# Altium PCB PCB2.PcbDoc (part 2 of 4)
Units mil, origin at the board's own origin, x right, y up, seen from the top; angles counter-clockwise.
Board outline 3980.79 x 2126 mil, 6 copper layers (Top Layer, Signal Layer 1, Signal Layer 2, Signal Layer 3, Signal Layer 4, Bottom Layer), stack 61.485 mil thick; 358 components, 190 nets, 1000 pads, 509 vias.
Unrouted connection lines stored in the file: 83.
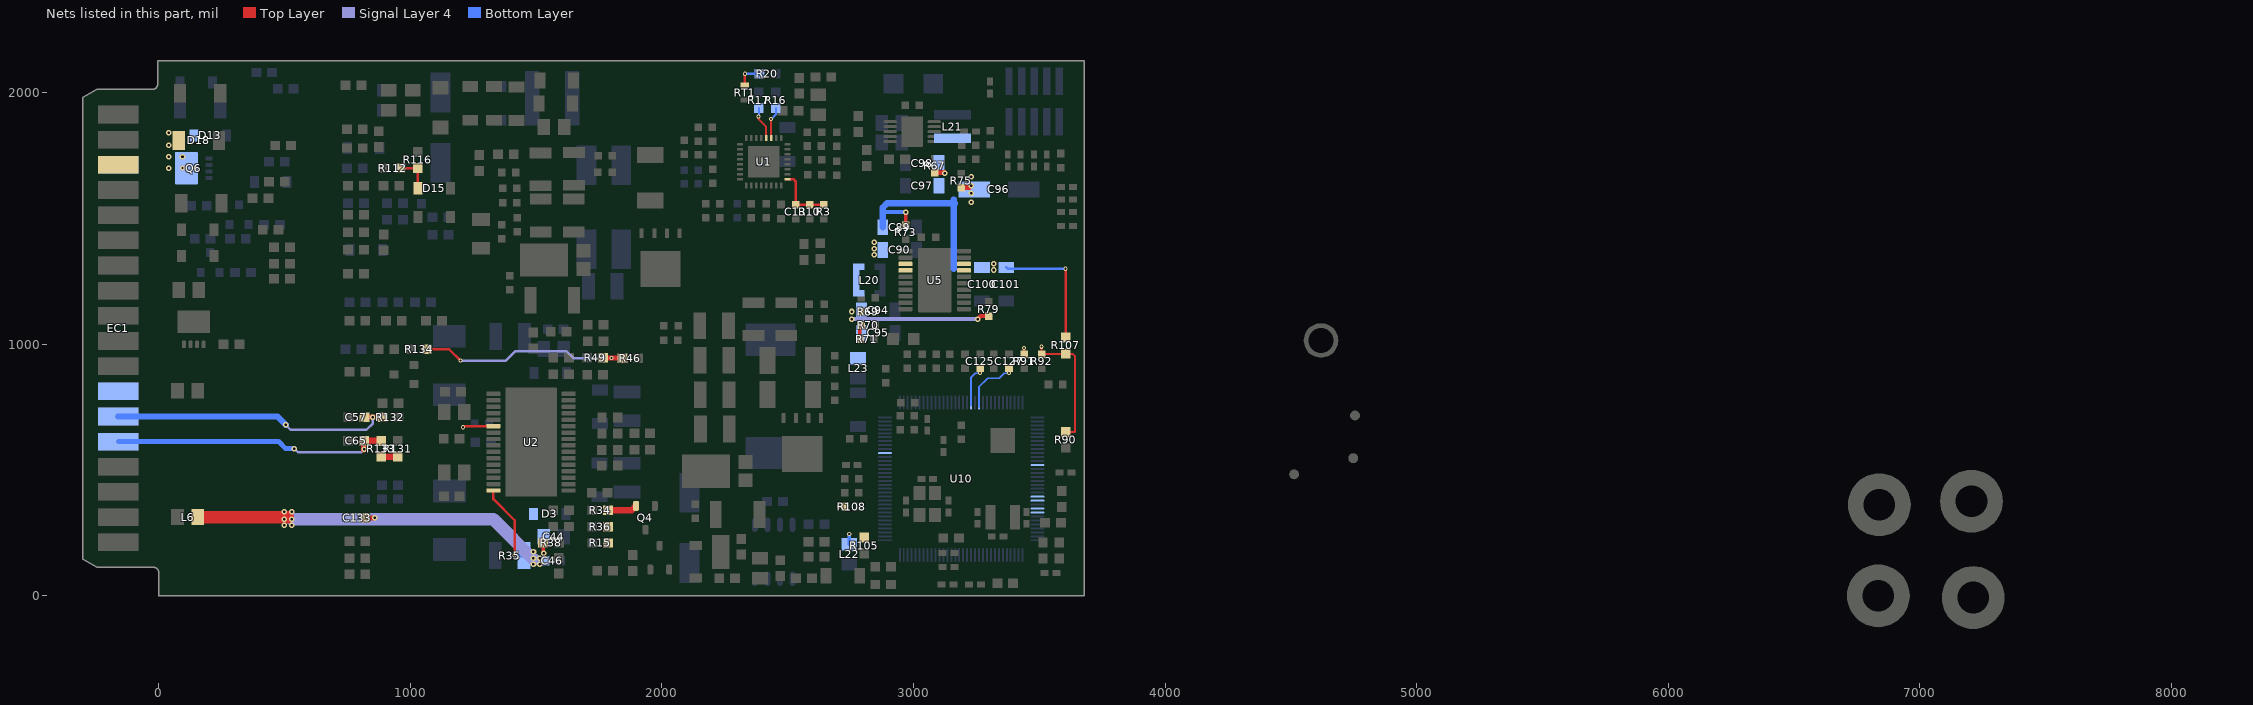
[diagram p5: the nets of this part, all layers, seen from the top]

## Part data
C1 C18: library part CMP-0007272-4, "CAP, CERM, 470 pF, 100 V, +/- 5%, C0G/NP0, 0603", Cap_Case=0603, Manufacturer=MuRata, PartNumber=GRM1885C2A471JA01D, Supplier Part Number 1=490-1367-1-ND, TempCo=C0G/NP0, Tolerance_%=5%, Value1=Unknown, ValueDisplayed=470pF
C2 C10 C19 C28 C29 C35 C36: library part CMP-0007082-4, "CAP, CERM, 0.01 uF, 100 V, +/- 10%, X7R, AEC-Q200 Grade 1, 0603", Cap_Case=0603, Manufacturer=TDK, PartNumber=CGA3E2X7R2A103K080AA, Supplier Part Number 1=445-5812-1-ND, TempCo=X7R, Tolerance_%=10%, Value1="0.235428 ohm", ValueDisplayed=0.01uF
C3 C9 C20 C27 C33: library part CMP-0007469-4, "CAP, CERM, 0.1 uF, 100 V, +/- 10%, X7R, 0603", Cap_Case=0603, Manufacturer=MuRata, PartNumber=GRM188R72A104KA35D, Supplier Part Number 1=490-3285-1-ND, TempCo=X7R, Tolerance_%=10%, Value1=Unknown, ValueDisplayed=0.1uF
C4 C21 C22 C23 C25 C26: library part CMP-0009120-1, "CAP, CERM, 10 uF, 50 V, +/- 20%, X7R, 1210", Cap_Case=1210, Manufacturer=TDK, Supplier Part Number 1=445-14933-1-ND, TempCo=X7R, Tolerance_%=20%, Value1=Unknown, Value2=50V, ValueDisplayed=10uF
C5 C6 C7 C8 C30: library part CMP-0009134-2, "CAP, CERM, 4.7 uF, 100 V, +/- 10%, X7S, 1210", Cap_Case=1210_220, Manufacturer=TDK, PartNumber=C3225X7S2A475K200AB, Supplier Part Number 1=445-6042-1-ND, TempCo=X7S, Tolerance_%=10%, Value1="0.004236 ohm", ValueDisplayed=4.7uF
C11: library part CMP-0011198-2, "CAP, AL, 33 uF, 80 V, +/- 20%, 1.3 ohm, AEC-Q200 Grade 2, SMD", Cap_Case=F, Manufacturer=Panasonic, Supplier Part Number 1=PCE3829CT-ND, Tolerance_%=20%, Value1="1.3 ohm", Value2=80V, ValueDisplayed=33uF
C12 C13 C34 C37: library part CMP-0007432-5, "CAP, CERM, 1000 pF, 50 V, +/- 10%, X7R, 0603", Cap_Case=0603, Manufacturer=MuRata, PartNumber=GRM188R71H102KA01D, Supplier Part Number 1=490-1494-1-ND, TempCo=X7R, Tolerance_%=10%, Value1=Unknown, Value2=50V, ValueDisplayed=1000pF
C14: library part CMP-0007423-4, "CAP, CERM, 0.047 uF, 25 V, +/- 10%, X7R, 0603", Cap_Case=0603, Manufacturer=MuRata, Supplier Part Number 1=490-1522-1-ND, TempCo=X7R, Tolerance_%=10%, Value1=Unknown, Value2=25V, ValueDisplayed=0.047uF
C15 C40: library part CMP-0006822-4, "CAP, CERM, 100 pF, 50 V, +/- 5%, C0G/NP0, 0603", Cap_Case=0603, Manufacturer="Wurth Elektronik", TempCo=C0G/NP0, Tolerance_%=5%, Value1=Unknown, Value2=50V, ValueDisplayed=100pF
C16: library part CMP-0008801-2, "CAP, CERM, 1 uF, 100 V, +/- 10%, X7R, 1206", Cap_Case=1206, Manufacturer=Samsung, PartNumber=CL31B105KCHNNNE, Supplier Part Number 1=1276-1838-1-ND, TempCo=X7R, Tolerance_%=10%, Value1=Unknown, ValueDisplayed=1uF
C17 C24 C31 C32 C42 C45 C49 C57 C65 C66 C74 C85 C87 C88: library part CMP-0007148-4, "CAP, CERM, 3300 pF, 100 V, +/- 10%, X7R, AEC-Q200 Grade 1, 0603", Cap_Case=0603, Manufacturer=MuRata, Supplier Part Number 1=GCM188R72A332KA37D-ND, TempCo=X7R, Tolerance_%=10%, Value1=Unknown, Value2=100V, ValueDisplayed=3300pF
C38 C39: library part CMP-0007499-4, "CAP, CERM, 2.2 uF, 16 V, +/- 10%, X7R, 0603", Cap_Case=0603, Manufacturer=MuRata, PartNumber=GRM188Z71C225KE43, Supplier Part Number 1=81-GRM188Z71C225KE3D, TempCo=X7R, Tolerance_%=10%, Value1=Unknown, Value2=16V, ValueDisplayed=2.2uF
C41: library part CMP-0007099-4, "CAP, CERM, 0.1 uF, 100 V, +/- 10%, X7S, AEC-Q200 Grade 1, 0603", Cap_Case=0603, Manufacturer=TDK, Supplier Part Number 1=445-6938-1-ND, TempCo=X7S, Tolerance_%=10%, Value1="0.04959 ohm", ValueDisplayed=0.1uF
C43 C47: library part CMP-0008791-2, "CAP, CERM, 2.2 uF, 100 V, +/- 20%, X7S, AEC-Q200 Grade 1, 1206_190", Alternate Manufacturer="Taiyo Yuden", Alternate PartNumber=HMJ316BC7225MLHTE, Cap_Case=1206, Manufacturer=TDK, Supplier Part Number 1=445-12947-1-ND, TempCo=X7S, Tolerance_%=20%, Value1=Unknown, Value2=100V, ValueDisplayed=2.2uF
C44 C64: library part CMP-0007981-2, "CAP, CERM, 0.22 uF, 100 V, +/- 10%, X7S, AEC-Q200 Grade 1, 0805", Alternate Manufacturer="Taiyo Yuden", Alternate PartNumber=HMJ212BB7224KGHT, Cap_Case=0805, Manufacturer=TDK, Supplier Part Number 1=445-7959-1-ND, TempCo=X7S, Tolerance_%=10%, Value1="0.019477 ohm", Value2=100V, ValueDisplayed=0.22uF
C46 C63: library part CMP-0007099-4, "CAP, CERM, 0.1 uF, 100 V, +/- 10%, X7S, AEC-Q200 Grade 1, 0603", Cap_Case=0603, Manufacturer=TDK, Supplier Part Number 1=445-6938-1-ND, TempCo=X7S, Tolerance_%=10%, Value1="0.04959 ohm", Value2=100V, ValueDisplayed=0.1uF
C48 C62: library part CMP-0007387-4, "CAP, CERM, 2200 pF, 16 V, +/- 10%, X7R, 0603", Cap_Case=0603, Manufacturer=MuRata, Supplier Part Number 1=GRM188R71C222KA01D-ND, TempCo=X7R, Tolerance_%=10%, Value1=Unknown, Value2=16V, ValueDisplayed=2200pF
C50 C60: library part CMP-0007077-5, "CAP, CERM, 0.1 uF, 25 V, +/- 10%, X7R, AEC-Q200 Grade 1, 0603", Cap_Case=0603, Manufacturer=TDK, Supplier Part Number 1=445-5667-1-ND, TempCo=X7R, Tolerance_%=10%, Value1=Unknown, Value2=25V, ValueDisplayed=0.1uF
C51 C61: library part CMP-0007467-4, "CAP, CERM, 1000 pF, 100 V, +/- 10%, X7R, 0603", Cap_Case=0603, Manufacturer=MuRata, Supplier Part Number 1=490-1472-1-ND, TempCo=X7R, Tolerance_%=10%, Value1=Unknown, Value2=100V, ValueDisplayed=1000pF
C52 C59: library part CMP-0009148-2, "CAP, CERM, 1.5 uF, 100 V, +/- 10%, X7R, AEC-Q200 Grade 1, 1210", Cap_Case=1210_220, Manufacturer=TDK, Supplier Part Number 1=445-13014-1-ND, TempCo=X7R, Tolerance_%=10%, Value1="0.003867 ohm", Value2=100V, ValueDisplayed=1.5uF
C53 C55: library part CMP-0007136-5, "CAP, CERM, 1 uF, 16 V, +/- 10%, X7R, AEC-Q200 Grade 1, 0603", Cap_Case=0603, Manufacturer=MuRata, Supplier Part Number 1=490-5241-6-ND, TempCo=X7R, Tolerance_%=10%, Value1=Unknown, Value2=16V, ValueDisplayed=1uF
C54 C56 C58: library part CMP-0085536-1, "CAP, CERM, 0.1 µF, 16 V,+/- 10%, X7R, 0603", Cap_Case=0603, Manufacturer="Samsung Electro-Mechanics", TempCo=X7R, Tolerance_%=10%, Value2=16V, ValueDisplayed=0.1µF
C67 C71 C72 C75 C80: library part CMP-0007725-2, "CAP, CERM, 0.1 uF, 50 V, +/- 10%, X7R, AEC-Q200 Grade 0, 0805", Cap_Case=0805, Manufacturer=Kemet, Supplier Part Number 1=399-6928-1-ND, TempCo=X7R, Tolerance_%=10%, Value1=Unknown, Value2=50V, ValueDisplayed=0.1uF
C68: library part CMP-0007143-4, "CAP, CERM, 0.01 uF, 50 V, +/- 10%, X7R, AEC-Q200 Grade 1, 0603", Cap_Case=0603, Manufacturer=MuRata, Supplier Part Number 1=490-4778-1-ND, TempCo=X7R, Tolerance_%=10%, Value1=Unknown, Value2=50V, ValueDisplayed=0.01uF
C69 C70 C76 C77 C78 C79: library part CMP-0008702-2, "CAP, CERM, 4.7 uF, 50 V, +/- 10%, X7R, 1206", Cap_Case=1206_180, Manufacturer=TDK, Supplier Part Number 1=445-8032-1-ND, TempCo=X7R, Tolerance_%=10%, Value1="0.003158 ohm", Value2=50V, ValueDisplayed=4.7uF
C73: library part CMP-0011177-2, "CAP, AL, 100 uF, 50 V, +/- 20%, 0.34 ohm, AEC-Q200 Grade 2, SMD", Cap_Case=F, Manufacturer=Panasonic, Supplier Part Number 1=PCE3809CT-ND, Tolerance_%=20%, Value1="0.34 ohm", Value2=50V, ValueDisplayed=100uF
C81: library part CMP-0860912-1, "CAP, CERM, 220 pF, 100 V,+/- 5%, C0G/NP0, AEC-Q200 Grade 1, 0603", Cap_Case=0603, Manufacturer=MuRata, TempCo=C0G/NP0, Tolerance_%=5%, Value2=100V, ValueDisplayed=220pF
C82 C83: library part CMP-0080704-2, "CAP, CERM, 15 pF, 100 V,+/- 5%, C0G/NP0, AEC-Q200 Grade 1, 0603", Cap_Case=0603, Manufacturer=MuRata, Supplier Part Number 1=490-4941-1-ND, TempCo=C0G/NP0, Tolerance_%=5%, Value2=100V, ValueDisplayed=15pF
C86 C133 C134: library part CMP-0007468-5, "CAP, CERM, 0.01 uF, 100 V, +/- 10%, X7R, 0603", Cap_Case=0603, Manufacturer=MuRata, Supplier Part Number 1=GRM188R72A103KA01D-ND, TempCo=X7R, Tolerance_%=10%, Value1=Unknown, Value2=100V, ValueDisplayed=0.01uF
C89 C90 C94 C95 C97 C98 C100 C101 C110: library part CMP-0008965-2, "CAP, CERM, 10 uF, 25 V, +/- 10%, X7R, 1206", Cap_Case=2220, Manufacturer=MuRata, PartNumber=GRM31CR71E106KA12L, Supplier Part Number 1=81-GRM31CR71E106KA12, TempCo=X7R, Tolerance_%=10%, Value1=Unknown, Value2=25V, ValueDisplayed=10uF
C91: library part CMP-0007378-5, "CAP, CERM, 0.1 uF, 16 V, +/- 10%, X7R, 0603", Cap_Case=0603, Manufacturer=MuRata, PartNumber=GRM188R71C104KA01D, Supplier Part Number 1=490-1532-1-ND, TempCo=X7R, Tolerance_%=10%, Value1=Unknown, Value2=16V, ValueDisplayed=0.1uF
C92: library part CMP-0007980-2, "CAP, CERM, 1 uF, 100 V, +/- 10%, X7S, AEC-Q200 Grade 1, 0805", Cap_Case=0805, Manufacturer=TDK, Supplier Part Number 1=445-6974-1-ND, TempCo=X7S, Tolerance_%=10%, Value1="0.008255 ohm", Value2=100V, ValueDisplayed=1uF
C93: library part CMP-0007969-2, "CAP, CERM, 0.1 uF, 100 V, +/- 10%, X7R, AEC-Q200 Grade 1, 0805", Cap_Case=0805, Manufacturer=TDK, Supplier Part Number 1=445-5827-1-ND, TempCo=X7R, Tolerance_%=10%, Value1="0.020726 ohm", Value2=100V, ValueDisplayed=0.1uF
C96: library part CMP-0010733-1, "CAP, AL, 100 uF, 16 V, +/- 20%, 0.26 ohm, AEC-Q200 Grade 2, SMD", Cap_Case=D, Manufacturer=Panasonic, Supplier Part Number 1=PCE4533CT-ND, Tolerance_%=20%, Value1="0.26 ohm", Value2=16V, ValueDisplayed=100uF
C99: library part CMP-0007405-4, "CAP, CERM, 1 uF, 25 V, +/- 10%, X7R, 0603", Cap_Case=0603, Manufacturer=MuRata, PartNumber=GRM188R71E105KA12D, Supplier Part Number 1=490-5307-1-ND, TempCo=X7R, Tolerance_%=10%, Value1=Unknown, Value2=25V, ValueDisplayed=1uF
C102: library part CMP-0006503-2, "CAP, CERM, 5 pF, 100 V, +/- 5%, C0G/NP0, 0402", Cap_Case=0402, Manufacturer=MuRata, Supplier Part Number 1=490-7291-1-ND, TempCo=C0G/NP0, Tolerance_%=5%, Value1=Unknown, Value2=100V, ValueDisplayed=5pF
C103: library part CMP-0007086-4, "CAP, CERM, 0.022 uF, 100 V, +/- 10%, X7R, AEC-Q200 Grade 1, 0603", Cap_Case=0603, Manufacturer=TDK, Supplier Part Number 1=445-5814-1-ND, TempCo=X7R, Tolerance_%=10%, Value1="0.083542 ohm", Value2=100V, ValueDisplayed=0.022uF
C104: library part CMP-0007453-4, "CAP, CERM, 3900 pF, 50 V, +/- 10%, X7R, 0603", Cap_Case=0603, Manufacturer=MuRata, PartNumber=GRM188R71H392KA01D, Supplier Part Number 1=490-1504-1-ND, TempCo=X7R, Tolerance_%=10%, Value1=Unknown, Value2=50V, ValueDisplayed=3900pF
C105 C106 C107 C108 C109 C113 C115 C119: library part CMP-0006641-2, "CAP, CERM, 0.1 uF, 16 V, +/- 10%, X7R, 0402", Cap_Case=0402, Manufacturer=MuRata, Supplier Part Number 1=490-3261-1-ND, TempCo=X7R, Tolerance_%=10%, Value1=Unknown, Value2=16V, ValueDisplayed=0.1uF
C111: library part CMP-0007339-5, "CAP, CERM, 2.2 uF, 16 V, +/- 10%, X5R, 0603", Cap_Case=0603, Manufacturer=MuRata, Supplier Part Number 1=490-3296-1-ND, TempCo=X5R, Tolerance_%=10%, Value1=Unknown, Value2=16V, ValueDisplayed=2.2uF
C112: library part CMP-0006563-2, "CAP, CERM, 1 uF, 10 V, +/- 10%, X5R, 0402", Cap_Case=0402, Manufacturer=MuRata, Supplier Part Number 1=490-3890-1-ND, TempCo=X5R, Tolerance_%=10%, Value1=Unknown, Value2=10V, ValueDisplayed=1uF
C114: library part CMP-0008968-2, "CAP, CERM, 2.2 uF, 50 V, +/- 10%, X7R, 1206", Cap_Case=1206, Manufacturer=MuRata, PartNumber=GRM31CR71H225KA88L, Supplier Part Number 1=490-3367-1-ND, TempCo=X7R, Tolerance_%=10%, Value1=Unknown, Value2=50V, ValueDisplayed=2.2uF
C116 C117 C118 C124 C125 C126 C127 C128 C129 C130 C131 C132: library part CMP-0006921-4, "CAP, CERM, 330 pF, 50 V, +/- 10%, X7R, 0603", Cap_Case=0603, Manufacturer=Kemet, Supplier Part Number 1=399-1073-1-ND, TempCo=X7R, Tolerance_%=10%, Value1=Unknown, Value2=50V, ValueDisplayed=330pF
C120 C121 C122 C123: library part CMP-0006415-2, "CAP, CERM, 12 pF, 50 V, +/- 5%, C0G/NP0, 0402", Cap_Case=0402, Manufacturer=MuRata, Supplier Part Number 1=14T3292, TempCo=C0G/NP0, Tolerance_%=5%, Value1=Unknown, Value2=50V, ValueDisplayed=12pF
D1 D2: library part CMP-0028754-2, "Diode, Schottky, 100 V, 3 A, AEC-Q101, PowerDI5", Manufacturer="Diodes Inc.", Value1=3A, Value2=0.76V
D3 D4: library part CMP-0080761-2, "Diode, Switching, 100 V, 0.25 A, AEC-Q101, SOD-123", Manufacturer=Vishay-Semiconductor, Value1=0.25A, Value2=1.25V
D5: library part CMP-0085086-1, "Diode, TVS, Bi, 28 V, 45.4 Vc, 400 W, 8.8 A, AEC-Q101, SMA (non-polarized)", Manufacturer=Littelfuse, Value1=45.4V
D6 D7 D13 D14: library part CMP-0750148-1, "Diode, Switching, 100 V, 0.3 A, AEC-Q101, SOD-123", Manufacturer="Diodes Inc.", Value1=0.3A, Value2=1.25V
D8 D9 D15 D16: library part CMP-0077593-3, "Diode, Zener, 3 V, 500 mW, SOD-123", Manufacturer=Vishay-Semiconductor, Power_W=500mW, Value1=0.5W
D10: library part CMP-0002980-3, "LED, Green, SMD", Color=Green, Manufacturer=OSRAM, PartNumber="LG R971-KN-1", Value1=W, Value2=2.2V
D11: library part CMP-0028837-2, "Diode, Schottky, 60 V, 2 A, AEC-Q101, SMA", Manufacturer=Vishay-Semiconductor, PartNumber=SS26SHE3_A/H, Value1=2A, Value2=0.75V
D12 D18 D19 D20: library part CMP-0028823-2, "Diode, Schottky, 30 V, 5 A, AEC-Q101, SMAF", Manufacturer="Fairchild Semiconductor", Value1=5A, Value2=0.54V
D17: library part CMP-0077570-3, "Diode, Zener, 10 V, 500 mW, AEC-Q101, SOD-123", Manufacturer=Vishay-Semiconductor, Power_W=500mW, Value1=0.5W
D21: library part CMP-0029032-2, "Diode, Switching, 100 V, 0.2 A, SOD-123", Manufacturer="ON Semiconductor", Value1=0.2A, Value2=1V
EC1: library part CMP-0077097-2, "Card Edge Footprint, 2.54mm, 18x2", Manufacturer="Sullins Connector Solutions"
FID1 FID2 FID3: library part CMP-0077181-1, "Fiducial mark.  There is nothing to buy or mount.", Manufacturer=N/A
H1 H2 H3 H4: library part CMP-0003617-1, "Machine Screw, Round, #4-40 x 1/4, Nylon, Philips panhead", Manufacturer="B&F Fastener Supply", Supplier Part Number 1=H542-ND
H5 H6 H7 H8: library part CMP-0003610-1, "Standoff, Hex, 0.5\"L #4-40 Nylon", Manufacturer=Keystone, Supplier Part Number 1=36-1902C-ND
H9 H10 H11 H12: library part CMP-0003620-1, "Bumpon, Hemisphere, 0.44 X 0.20, Clear", Manufacturer=3M, Supplier Part Number 1=SJ5303-7-ND
J3: library part CMP-0075629-2, "Header, 1.27mm, 5x2, Gold, Black, SMT", Color=Black, Current_A=3.3A, Manufacturer=Samtec, PartNumber=FTSH-105-01-F-DV, Supplier Part Number 1=SAM8795-ND
L1: library part CMP-0084138-1, "Inductor, Shielded, 22 µH, 6.9 A, 0.0341 ohm, AEC-Q200 Grade 0, SMD", Manufacturer=TDK, Value1="0.0341 ohm", Value2=6.9A, ValueDisplayed=22µH
L2 L5 L6 L8 L9: library part CMP-0003069-1, "Ferrite Bead, 33 ohm @ 100 MHz, 4 A, 0805", Manufacturer="Wurth Elektronik", Supplier Part Number 1=732-4636-1-ND, Value1="0.008 ohm", Value2=4A, ValueDisplayed="33 ohm"
L3: library part CMP-0012870-2, "Coupled inductor, 33 uH, 5.6 A, 0.15 ohm, TH", Manufacturer=Coilcraft, ValueDisplayed=33uH
L4 L7: library part CMP-0081480-2, "Inductor, Shielded, Metal Composite, 68 µH, 1.8 A, 0.316 ohm, SMD", Manufacturer=TDK, Value1="0.316 ohm", Value2=1.8A, ValueDisplayed=68µH
L10: library part CMP-0061017-2, "Inductor, Shielded, Composite, 3.3 µH, 8 A, 0.02081 ohm, AEC-Q200 Grade 1, SMD", Manufacturer=Coilcraft, Value1="0.02081 ohm", Value2=8A, ValueDisplayed=3.3µH
L20: library part CMP-0060436-1, "Inductor, Shielded Drum Core, Ferrite, 2.2 uH, 1.1 A, 0.22 ohm, SMD", Manufacturer=Coilcraft, Value1="0.22 ohm", Value2=1.1A, ValueDisplayed=2.2uH
L21: library part CMP-0061649-2, "Inductor, Shielded, Composite, 15 uH, 2.8 A, 0.109 ohm, SMD", Manufacturer=Coilcraft, PartNumber=XAL4040-153MEB, Supplier Part Number 1=994-XAL4040-153MEB, Value1="0.109 ohm", Value2=2.8A, ValueDisplayed=15uH
L22: library part CMP-0003363-1, "Ferrite Bead, 220 ohm @ 100 MHz, 2 A, 0805", Manufacturer=MuRata, PartNumber=BLM21PG221SN1D, Supplier Part Number 1=490-1054-1-ND, Value1="0.045 ohm", Value2=2A, ValueDisplayed="220 ohm"
L23: library part CMP-0003306-1, "Ferrite Bead, 60 ohm @ 100 MHz, 3 A, 0805", Manufacturer="Taiyo Yuden", PartNumber=BKP2125HS600-T, Supplier Part Number 1=587-1932-1-ND, Value1="0.025 ohm", Value2=3A, ValueDisplayed="60 ohm"
LBL1: library part CMP-0003625-1, "Thermal Transfer Printable Labels, 0.650\" W x 0.200\" H - 10,000 per roll", Manufacturer=Brady, Supplier Part Number 1=97C5133
Logo1: library part CMP-0074838-1, "Texas Instrument Corporate Signature"
Logo2: library part CMP-0074844-1
Logo3: library part CMP-0074847-1, "FCC_disclaimer"
Logo4: library part CMP-0074769-1
Q1 Q3: library part CMP-0086155-1, "MOSFET, N-CH, 80 V, 60 A, AEC-Q101, PowerPAK_SO-8L", Alternate Manufacturer=None, Manufacturer=Vishay-Siliconix, Value1="? ohm", Value2="36 nC"
Q4: library part CMP-0000092-3, "MOSFET, P-CH, -20 V, -3.7 A, SOT-23", Alternate Manufacturer=None, Manufacturer=Vishay-Siliconix, Value1=0.03, Value2="12.5 nC"
Q5: library part CMP-0000419-2, "Transistor, NPN, 40 V, 0.2 A, SOT-23", Manufacturer="ON Semiconductor", Supplier Part Number 1=MMBT3904LT1GOSCT-ND, Value1="0.2 A", Value2=300
Q6: library part CMP-0000123-4, "MOSFET, P-CH, -30 V, -13.9 A, PowerPAK 1212", Alternate Manufacturer=None, Manufacturer=Vishay-Siliconix, Value1=0.022, Value2="20.5 nC"
Q7 Q8 Q10: library part CMP-0087176-1, "MOSFET N-CH 100V 170MA SOT23-3", Manufacturer="Diodes Incorporated"
Q9: library part CMP-0000752-2, "MOSFET, N-CH, 40 V, 12 A, AEC-Q101, PowerPAK 1212", Alternate Manufacturer=None, Manufacturer=Vishay-Siliconix, Supplier Part Number 1=SQS840EN-T1_GE3-ND, Value1=0, Value2="15 nC"
R1 R18: library part CMP-0016180-3, "RES, 7.5, 5%, 0.75 W, AEC-Q200 Grade 0, 2010", Manufacturer=Vishay-Dale, PartNumber=CRCW20107R50JNEF, Power_W=750mW, Supplier Part Number 1=541-7.5WCT-ND, TempCo="200 ppm/C", Tolerance_%=5%, Value2=0.75W, Value_Code=7R50, ValueDisplayed=7.5
R2 R14 R25: library part CMP-0025697-4, "RES, 0, 5%, 0.1 W, AEC-Q200 Grade 0, 0603", Manufacturer=Vishay-Dale, Power_W=100mW, Supplier Part Number 1=541-0.0GCT-ND, TempCo="200 ppm/C", Tolerance_%=5%, Value2=0.1W, Value_Code=0000, ValueDisplayed=0
R3 R58 R60 R116 R118 R121: library part CMP-0021990-4, "RES, 100 k, 1%, 0.1 W, AEC-Q200 Grade 0, 0603", Manufacturer=Vishay-Dale, Power_W=100mW, Supplier Part Number 1=541-100KHCT-ND, TempCo="100 ppm/C", Tolerance_%=1%, Value2=0.1W, Value_Code=100k
R4 R30: library part CMP-0021991-4, "RES, 100, 1%, 0.1 W, AEC-Q200 Grade 0, 0603", Manufacturer=Vishay-Dale, PartNumber=CRCW0603100RFKEA, Power_W=100mW, Supplier Part Number 1=541-100HCT-ND, TempCo="100 ppm/C", Tolerance_%=1%, Value2=0.1W, Value_Code=100R, ValueDisplayed=100
R5 R8 R21 R38 R40: library part CMP-0022200-4, "RES, 200 k, 1%, 0.1 W, AEC-Q200 Grade 0, 0603", Manufacturer=Vishay-Dale, Power_W=100mW, Supplier Part Number 1=541-200KHCT-ND, TempCo="100 ppm/C", Tolerance_%=1%, Value2=0.1W, Value_Code=200k
R6 R9 R32: library part CMP-0016519-2, "RES, 0.04, 1%, 1 W, 2010", Manufacturer="Stackpole Electronics Inc", Power_W=1W, Supplier Part Number 1=CSRN2010FK40L0CT-ND, TempCo="250 ppm/C", Tolerance_%=1%, Value_Code=R040, ValueDisplayed=0.04
R7 R13 R16 R17 R20 R46 R48 R50 R99 R102 R103 R105: library part CMP-0023341-3, "RES, 10.0 k, 1%, 0.1 W, AEC-Q200 Grade 0, 0603", Manufacturer="Stackpole Electronics Inc", Power_W=100mW, Supplier Part Number 1=RMCF0603FT10K0CT-ND, TempCo="100 ppm/C", Tolerance_%=1%, Value2=0.1W, Value_Code=10k0, ValueDisplayed=10.0k
R10: library part CMP-0022450-4, "RES, 4.12 k, 1%, 0.1 W, AEC-Q200 Grade 0, 0603", Manufacturer=Vishay-Dale, Power_W=100mW, Supplier Part Number 1=541-4.12KHCT-ND, TempCo="100 ppm/C", Tolerance_%=1%, Value2=0.1W, Value_Code=4k12, ValueDisplayed=4.12k
R11: library part CMP-0021009-3, "RES, 1.00, 1%, 0.125 W, AEC-Q200 Grade 0, 0805", Manufacturer=Vishay-Dale, PartNumber=CRCW08051R00FKEA, Power_W=125mW, Supplier Part Number 1=72M6849, TempCo="100 ppm/C", Tolerance_%=1%, Value2=0.125W, Value_Code=1R00, ValueDisplayed=1.00
R12: library part CMP-0022687-3, "RES, 14.7 k, 1%, 0.1 W, AEC-Q200 Grade 0, 0603", Manufacturer=Panasonic, Power_W=100mW, Supplier Part Number 1=P14.7KHCT-ND, TempCo="100 ppm/C", Tolerance_%=1%, Value2=0.1W, Value_Code=14k7, ValueDisplayed=14.7k
R15 R28 R90 R107: library part CMP-0022002-4, "RES, 10.0 M, 1%, 0.1 W, AEC-Q200 Grade 0, 0603", Manufacturer=Vishay-Dale, Power_W=100mW, Supplier Part Number 1=541-10.0MHCT-ND, TempCo="100 ppm/C", Tolerance_%=1%, Value2=0.1W, Value_Code=10M0, ValueDisplayed=10.0M
R19: library part CMP-0017835-2, "RES, 0.165, 1%, 0.25 W, 1206", Manufacturer="Yageo America", Power_W=250mW, Supplier Part Number 1=311-0.165ANCT-ND, TempCo="75 ppm/C", Tolerance_%=1%, Value2=0.25W, Value_Code=R165, ValueDisplayed=0.165
R22: library part CMP-0022408-4, "RES, 402 k, 1%, 0.1 W, AEC-Q200 Grade 0, 0603", Manufacturer=Vishay-Dale, Power_W=100mW, Supplier Part Number 1=541-402KHCT-ND, TempCo="100 ppm/C", Tolerance_%=1%, Value2=0.1W, Value_Code=402k
R23 R39 R41 R44 R54 R55 R56 R57 R59 R61 R62 R66 R111 R112 R113 R114 R115 R117 R120 R123 R124 R125 R126 R128 R129 R130 R131 R135 R136 R140 R141: library part CMP-0021998-4, "RES, 10.0 k, 1%, 0.1 W, AEC-Q200 Grade 0, 0603", Manufacturer=Vishay-Dale, Power_W=100mW, Supplier Part Number 1=541-10.0KHCT-ND, TempCo="100 ppm/C", Tolerance_%=1%, Value2=0.1W, Value_Code=10k0, ValueDisplayed=10.0k
R24 R47: library part CMP-0021990-4, "RES, 100 k, 1%, 0.1 W, AEC-Q200 Grade 0, 0603", Manufacturer=Vishay-Dale, PartNumber=CRCW0603100KFKEA, Power_W=100mW, Supplier Part Number 1=541-100KHCT-ND, TempCo="100 ppm/C", Tolerance_%=1%, Value2=0.1W, Value_Code=100k
R26 R27: library part CMP-0022003-4, "RES, 10.0, 1%, 0.1 W, AEC-Q200 Grade 0, 0603", Manufacturer=Vishay-Dale, PartNumber=CRCW060310R0FKEA, Power_W=100mW, Supplier Part Number 1=541-10.0HCT-ND, TempCo="100 ppm/C", Tolerance_%=1%, Value2=0.1W, Value_Code=10R0, ValueDisplayed=10.0
R29: library part CMP-0022665-4, "RES, 9.09 k, 1%, 0.1 W, AEC-Q200 Grade 0, 0603", Manufacturer=Vishay-Dale, Power_W=100mW, Supplier Part Number 1=541-9.09KHCT-ND, TempCo="100 ppm/C", Tolerance_%=1%, Value2=0.1W, Value_Code=9k09, ValueDisplayed=9.09k
R31: library part CMP-0022036-4, "RES, 130 k, 1%, 0.1 W, AEC-Q200 Grade 0, 0603", Manufacturer=Vishay-Dale, Power_W=100mW, Supplier Part Number 1=541-130KHCT-ND, TempCo="100 ppm/C", Tolerance_%=1%, Value2=0.1W, Value_Code=130k
R33: library part CMP-0022440-4, "RES, 47.5, 1%, 0.1 W, AEC-Q200 Grade 0, 0603", Manufacturer=Vishay-Dale, Power_W=100mW, Supplier Part Number 1=541-47.5HCT-ND, TempCo="100 ppm/C", Tolerance_%=1%, Value2=0.1W, Value_Code=47R5, ValueDisplayed=47.5
R34 R49: library part CMP-0022068-4, "RES, 15.8 k, 1%, 0.1 W, AEC-Q200 Grade 0, 0603", Manufacturer=Vishay-Dale, Power_W=100mW, Supplier Part Number 1=541-15.8KHCT-ND, TempCo="100 ppm/C", Tolerance_%=1%, Value2=0.1W, Value_Code=15k8, ValueDisplayed=15.8k
R35 R52: library part CMP-0015068-3, "RES, 0.1, 1%, 0.33 W, AEC-Q200 Grade 1, 1210", Alternate Manufacturer=Yageo, Alternate PartNumber=RL1210FR-070R1L, Manufacturer=Panasonic, Power_W=330mW, Supplier Part Number 1=P100NACT-ND, TempCo="100 ppm/C", Tolerance_%=1%, Value2=0.33W, Value_Code=R100, ValueDisplayed=0.1
R36 R43 R51 R108 R109 R110 R122 R127 R132 R133 R134 R137 R138 R139 R142 R143: library part CMP-0022109-5, "RES, 1.00 k, 1%, 0.1 W, AEC-Q200 Grade 0, 0603", Manufacturer=Vishay-Dale, Power_W=100mW, Supplier Part Number 1=541-1.00KHCT-ND, TempCo="100 ppm/C", Tolerance_%=1%, Value2=0.1W, Value_Code=1k00, ValueDisplayed=1.00k
R37 R53: library part CMP-0022324-4, "RES, 30.1 k, 1%, 0.1 W, AEC-Q200 Grade 0, 0603", Manufacturer=Vishay-Dale, Power_W=100mW, Supplier Part Number 1=541-30.1KHCT-ND, TempCo="100 ppm/C", Tolerance_%=1%, Value2=0.1W, Value_Code=30k1, ValueDisplayed=30.1k
R42 R45: library part CMP-0025874-4, "RES, 0, 5%, 0.1 W, AEC-Q200 Grade 0, 0603", Manufacturer=Panasonic, Power_W=100mW, Supplier Part Number 1=P0.0GCT-ND, TempCo="600 ppm/C", Tolerance_%=5%, Value2=0.1W, Value_Code=0000, ValueDisplayed=0
R63 R64 R65 R100 R144: library part CMP-0022003-4, "RES, 10.0, 1%, 0.1 W, AEC-Q200 Grade 0, 0603", Manufacturer=Vishay-Dale, Power_W=100mW, Supplier Part Number 1=541-10.0HCT-ND, TempCo="100 ppm/C", Tolerance_%=1%, Value2=0.1W, Value_Code=10R0, ValueDisplayed=10.0
R67 R70 R79: library part CMP-0023133-5, "RES, 47.0 k, 1%, 0.1 W, 0603", Manufacturer=Yageo, PartNumber=RC0603FR-0747KL, Power_W=100mW, Supplier Part Number 1=311-47.0KHRCT-ND, TempCo="100 ppm/C", Tolerance_%=1%, Value2=0.1W, Value_Code=47k0, ValueDisplayed=47.0k
R68: library part CMP-0022701-2, "RES, 402 k, 1%, 0.1 W, AEC-Q200 Grade 0, 0603", Manufacturer=Panasonic, Power_W=100mW, Supplier Part Number 1=P402KHCT-ND, TempCo="100 ppm/C", Tolerance_%=1%, Value2=0.1W, Value_Code=402k
R69: library part CMP-0023026-5, "RES, 31.6 k, 1%, 0.1 W, 0603", Manufacturer=Yageo, PartNumber=RC0603FR-0731K6L, Power_W=100mW, Supplier Part Number 1=311-31.6KHRCT-ND, TempCo="100 ppm/C", Tolerance_%=1%, Value2=0.1W, Value_Code=31k6, ValueDisplayed=31.6k
R71: library part CMP-0023235-5, "RES, 680, 1%, 0.1 W, 0603", Manufacturer=Yageo, PartNumber=RC0603FR-07680RL, Power_W=100mW, Supplier Part Number 1=311-680HRCT-ND, TempCo="100 ppm/C", Tolerance_%=1%, Value2=0.1W, Value_Code=680R, ValueDisplayed=680
R72 R77: library part CMP-0021998-4, "RES, 10.0 k, 1%, 0.1 W, AEC-Q200 Grade 0, 0603", Manufacturer=Vishay-Dale, PartNumber=CRCW060310K0FKEA, Power_W=100mW, Supplier Part Number 1=541-10.0KHCT-ND, TempCo="100 ppm/C", Tolerance_%=1%, Value2=0.1W, Value_Code=10k0, ValueDisplayed=10.0k
R73: library part CMP-0025821-4, "RES, 4.7, 5%, 0.1 W, AEC-Q200 Grade 0, 0603", Manufacturer=Vishay-Dale, PartNumber=CRCW06034R70JNEA, Power_W=100mW, Supplier Part Number 1=541-4.7GCT-ND, TempCo="200 ppm/C", Tolerance_%=5%, Value2=0.1W, Value_Code=4R70, ValueDisplayed=4.7
R74: library part CMP-0022038-4, "RES, 133 k, 1%, 0.1 W, AEC-Q200 Grade 0, 0603", Manufacturer=Vishay-Dale, PartNumber=CRCW0603133KFKEA, Power_W=100mW, Supplier Part Number 1=541-133KHCT-ND, TempCo="100 ppm/C", Tolerance_%=1%, Value2=0.1W, Value_Code=133k
R75: library part CMP-0022486-4, "RES, 52.3 k, 1%, 0.1 W, AEC-Q200 Grade 0, 0603", Manufacturer=Vishay-Dale, PartNumber=CRCW060352K3FKEA, Power_W=100mW, Supplier Part Number 1=541-52.3KHCT-ND, TempCo="100 ppm/C", Tolerance_%=1%, Value2=0.1W, Value_Code=52k3, ValueDisplayed=52.3k
R76: library part CMP-0022659-4, "RES, 95.3 k, 1%, 0.1 W, AEC-Q200 Grade 0, 0603", Manufacturer=Vishay-Dale, PartNumber=CRCW060395K3FKEA, Power_W=100mW, Supplier Part Number 1=541-95.3KHCT-ND, TempCo="100 ppm/C", Tolerance_%=1%, Value2=0.1W, Value_Code=95k3, ValueDisplayed=95.3k
R78: library part CMP-0022581-4, "RES, 71.5 k, 1%, 0.1 W, AEC-Q200 Grade 0, 0603", Manufacturer=Vishay-Dale, Power_W=100mW, Supplier Part Number 1=541-71.5KHCT-ND, TempCo="100 ppm/C", Tolerance_%=1%, Value2=0.1W, Value_Code=71k5, ValueDisplayed=71.5k
R80: library part CMP-0026763-1, "RES, 100, 1%, 0.063 W, AEC-Q200 Grade 0, 0402", Manufacturer="Stackpole Electronics Inc", Power_W=63mW, Supplier Part Number 1=RMCF0402JT100RCT-ND, TempCo="100 ppm/C", Tolerance_%=1%, Value2=0.063W, Value_Code=100R, ValueDisplayed=100
R81 R82 R83 R84: library part CMP-0026754-1, "RES, 10.0 k, 1%, 0.063 W, AEC-Q200 Grade 0, 0402", Manufacturer="Stackpole Electronics Inc", Power_W=63mW, Supplier Part Number 1=RMCF0402FT10K0CT-ND, TempCo="100 ppm/C", Tolerance_%=1%, Value2=0.063W, Value_Code=10k0, ValueDisplayed=10.0k
R85 R86 R87 R88: library part CMP-0026759-1, "RES, 33.0, 1%, 0.063 W, AEC-Q200 Grade 0, 0402", Manufacturer="Stackpole Electronics Inc", Power_W=63mW, Supplier Part Number 1=RMCF0402FT33R0CT-ND, TempCo="100 ppm/C", Tolerance_%=1%, Value2=0.063W, Value_Code=33R0, ValueDisplayed=33.0
R89 R91 R92 R94 R96: library part CMP-0025697-4, "RES, 0, 5%, 0.1 W, AEC-Q200 Grade 0, 0603", Manufacturer=Vishay-Dale, PartNumber=CRCW06030000Z0EA, Power_W=100mW, Supplier Part Number 1=541-0.0GCT-ND, TempCo="200 ppm/C", Tolerance_%=5%, Value2=0.1W, Value_Code=0000, ValueDisplayed=0
R93: library part CMP-0022986-5, "RES, 2.20 k, 1%, 0.1 W, 0603", Manufacturer=Yageo, PartNumber=RC0603FR-072K2L, Power_W=100mW, Supplier Part Number 1=311-2.20KHRCT-ND, TempCo="100 ppm/C", Tolerance_%=1%, Value2=0.1W, Value_Code=2k20, ValueDisplayed=2.20k
R95: library part CMP-0023169-5, "RES, 51.0, 1%, 0.1 W, 0603", Manufacturer=Yageo, Power_W=100mW, Supplier Part Number 1=311-51.0HRCT-ND, TempCo="100 ppm/C", Tolerance_%=1%, Value2=0.1W, Value_Code=51R0, ValueDisplayed=51.0
R97: library part CMP-0022138-4, "RES, 1.00 M, 1%, 0.1 W, AEC-Q200 Grade 0, 0603", Manufacturer=Vishay-Dale, Power_W=100mW, Supplier Part Number 1=541-1.00MHCT-ND, TempCo="100 ppm/C", Tolerance_%=1%, Value2=0.1W, Value_Code=1M00, ValueDisplayed=1.00M
R98 R119: library part CMP-0022747-4, "RES, 10.0 M, 1%, 0.1 W, 0603", Manufacturer=Yageo, Power_W=100mW, Supplier Part Number 1=311-10.0MHRCT-ND, TempCo="100 ppm/C", Tolerance_%=1%, Value2=0.1W, Value_Code=10M0, ValueDisplayed=10.0M
R101: library part CMP-0022457-4, "RES, 4.87 k, 1%, 0.1 W, AEC-Q200 Grade 0, 0603", Manufacturer=Vishay-Dale, Power_W=100mW, Supplier Part Number 1=541-4.87KHCT-ND, TempCo="100 ppm/C", Tolerance_%=1%, Value2=0.1W, Value_Code=4k87, ValueDisplayed=4.87k
R104: library part CMP-0027004-2, "RES, 0, 5%, 0.063 W, 0402", Manufacturer="Yageo America", Power_W=63mW, Supplier Part Number 1=311-0.0JRCT-ND, TempCo="200 ppm/C", Tolerance_%=5%, Value2=0.063W, Value_Code=0000, ValueDisplayed=0
R106: library part CMP-0026889-5, "RES, 2.0 k, 5%, 0.063 W, AEC-Q200 Grade 0, 0402", Manufacturer=Vishay-Dale, Power_W=63mW, Supplier Part Number 1=541-2.0KJCT-ND, TempCo="200 ppm/C", Tolerance_%=5%, Value2=0.063W, Value_Code=2k00, ValueDisplayed=2.0k
RT1: library part CMP-0002534-3, "Thermistor NTC, 100k ohm, 5%, 0603", Manufacturer=MuRata, Power_W=100mW, Supplier Part Number 1=490-2430-1-ND, Tolerance_%=5%
TP1: library part CMP-0055152-1, "Test Point, Miniature, SMT", Manufacturer=Keystone, Supplier Part Number 1=36-5015TR-ND
TP3: library part CMP-0055113-1, "Terminal, Turret, TH, Double", Manufacturer=Keystone, PartNumber=1502-2, Supplier Part Number 1=36-1502-2-ND
U1: library part CMP-0084188-3, "Dual Channel Constant Voltage and Constant Current Controller with SPI Interface, RHM0032C (VQFNP-32)", Alternate Manufacturer="Texas Instruments", Operating Temperature Range="-40 to 125 C", Rating=Automotive
U2: library part CMP-0085387-1, "4.5 to 65-V Input Dual 1.6-A Synchronous Buck LED Driver with SPI Control, DAP0032A (HTSSOP-32)", Alternate Manufacturer="Texas Instruments", Alternate PartNumber=TPS92520QDAPQ1
U3: library part CMP-0079113-2, "Local Interconnect Network (LIN) Transceiver with Dominant State Timeout, D0008A (SOIC-8)", Alternate Manufacturer="Texas Instruments", Alternate PartNumber=TLIN1029DQ1
U4: library part CMP-0074018-2, "Automotive 3.5V to 60V, 1.5A Step Down SWIFT(TM) Converter with Eco-Mode(TM), DGQ0010D (VSSOP-10)", Alternate Manufacturer="Texas Instruments", PartNumber=TPS57160QDGQRQ1
U5: library part CMP-0066062-3, "Dual 2.0A, High Frequency Synchronous Step-Down DC-DC  Regulator, PWP0020A (HTSSOP-20)", Alternate Manufacturer="Texas Instruments", Alternate PartNumber=LM26420Q0XMH/NOPB, Operating Temperature Range="-40 to 125 C", PartNumber=LM26420Q0XMHX/NOPB, Rating=Automotive
U10: library part CMP-0077953-1, "MSP432E401YTPDT, PDT0128A (TQFP-128)", Alternate Manufacturer="Texas Instruments", Alternate PartNumber=MSP432E401YTPDTR
Y1: library part CMP-0004653-5, "Crystal, 32.768 kHz,  SMD", Frequency_Fixed=32.768kHz, Frequency Stability=+/-20ppm, Manufacturer="Citizen FineDevice", Supplier Part Number 1=695-CMR200T32.7KY-U
Y2: library part CMP-0004652-3, "Crystal, 25 MHz, 8pF, SMD", Frequency_Fixed=25MHz, Frequency Stability=+/-30ppm, Manufacturer=NDK, Supplier Part Number 1=644-1259-1-ND
ZZ1: library part CMP-0003616-3
ZZ2: library part CMP-0077236-1
ZZ3: library part CMP-0077237-1
ZZ4: library part CMP-0077238-1

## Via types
v1: diameter 22, hole 10, Top Layer to Bottom Layer, tented both sides, 287 vias
v2: diameter 16, hole 8, Top Layer to Bottom Layer, tented both sides, 129 vias
v3: diameter 19.68, hole 7.87, Top Layer to Bottom Layer, 47 vias
v4: diameter 19.68, hole 7.87, Top Layer to Bottom Layer, tented both sides, 28 vias
v5: diameter 50, hole 28, Top Layer to Bottom Layer, 18 vias

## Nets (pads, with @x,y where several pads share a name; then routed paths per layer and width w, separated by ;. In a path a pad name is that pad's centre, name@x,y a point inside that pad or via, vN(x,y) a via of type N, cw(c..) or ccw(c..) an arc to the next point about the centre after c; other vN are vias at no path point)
3V3: C94.1 C95.1 L20.2 L22.1 L23.1 R69.1 R70.2 R71.2 R79.2 | length 640
  Top Layer w15: R71.2@2787,1020 R70.2@2787,1070 ; v1(3255,1100) 3267,1112 R79.2@3300,1112
  Signal Layer 4 w15: v1(2755,1100) v1(3255,1100)
  Bottom Layer w15: L22.1@2745,205 v2(2745,245)
  other v1: 2755,1130
5V: C89.1 C90.1 C96.1 C97.1 C98.1 C100.1 C101.1 L21.2 Q4.2 R34.2 R46.2 R49.2 R67.2 R73.1 R75.2 R107.1 R134.2 U5.3 U5.4 U5.17 U5.18 | length 2359.9
  Top Layer w10: R134.2@1066.5,980 1155,980 v2(1200,935) ; R107.1@3605,1026.5 v2(3605,1300)
  Top Layer w15: R73.1@2970,1473 v1(2970,1525)
  Top Layer w20: R49.2@1766.5,946.77 1768.27,945 v2(1800,945) R46.2@1843.5,945 ; R67.2@3085,1682 v1@3123,1682 ; R75.2@3190,1622 3222,1622 v1(3230,1630)
  Top Layer w25: R34.2@1786.5,340 1880.35,340 Q4.2@1897.6,357.24
  Signal Layer 4 w10: v2(1200,935) 1380,935 1417.87,972.87 1620.33,972.87 1648.2,945 v2(1800,945)
  Bottom Layer w10: C101.1@3369.21,1305.25 3374.46,1300 v2(3605,1300)
  Bottom Layer w15: 2878.07,1523.07 2880,1525 v1(2970,1525)
  Bottom Layer w25: C89.1@2878.07,1465 2878.07,1523.07 2878.07,1543.07 2895,1560 3165,1560 ; 3160,1300 3160,1575
  other v1: 3320,1295 3320,1320 2845,1355 2845,1380 2845,1405 3230,1565 3230,1600 3230,1665 3125,1680
A_NTC1: C127.1 R20.1 RT1.2 U10.21 | length 345.9
  Top Layer w10: RT1.2@2330,2030 v2(2330,2075) ; v2(3380,885) C127.1@3380,905
  Bottom Layer w7: U10.21@3260.87,750 3260.87,830.87 3295,865 3340.54,865 3360.54,885 v2(3380,885)
  Bottom Layer w10: v2(2330,2075) R20.1@2388.5,2075
BPWM1: R16.1 R91.2 U1.3 | length 150.7
  Top Layer w8: U1.3@2434.53,1819.49 v2(2434.53,1894.53) ; R91.2@3440,961 v2(3440,985)
  Bottom Layer w8: v2(2434.53,1894.53) 2453,1913 R16.1@2453,1938.5
BPWM2: R17.1 R90.2 R92.2 R107.2 U1.4 | length 632.5
  Top Layer w8: v2(2385,1905) 2385,1895 2414.84,1865.16 U1.4@2414.84,1819.49 ; v2(3510,990) R92.2@3510,961 3634,961 3641.5,953.5 3641.5,651.5 R90.2@3605,651.5
  Bottom Layer w8: v2@2386,1906 R17.1@2386,1938.5
BUCK_nFLT_1-2: R105.1 R108.2 U2.22 | length 144.5
  Top Layer w10: v2(1210,670) 1214.57,674.57 U2.22@1330.59,674.57 ; v2(2705,355) R108.2@2727,355
DRL_NTC: C125.1 R131.1 R133.2 U10.19 | length 241.2
  Top Layer w10: v2(3265,885) C125.1@3265,905
  Top Layer w25: R133.2@885,552.95 R131.1@950,552.95
  Bottom Layer w7: U10.19@3229.37,755 3229.37,868.83 3245.54,885 v2(3265,885)
DRLPOS: D13.2 D18.2 EC1.5 EC1.6 Q6.5 Q6.6 Q6.7 Q6.8 Q6.9@110.67,1700
  other v1: 40,1700 40,1745 95,1745 40,1790 40,1840
  other v3: 94.72,1700 144.92,1700
DRLPOS+: C44.1 C46.1 C133.1 D3.1 L6.1 R35.2 R38.2 U2.32 | length 1794.3
  Top Layer w10: U2.32@1330.59,418.66 1330.59,384.41 1414.69,300.31 v2(1414.69,160)
  Top Layer w15: R38.2@1528.5,210 1528.5,171.5 v1(1530,170)
  Top Layer w20: C133.1@821.5,310 v1(860,310)
  Top Layer w50: L6.1@155,312.99 512.99,312.99
  Signal Layer 4 w50: v1(530,305) 1330,305 v1@1490,145
  Bottom Layer w15: v2(1414.69,160) R35.2@1452.09,160
  other v1: 1490,125 1515,125 1490,150 1515,150 1490,175 500,280 530,280 500,305 500,335 530,335
DRLPOS-: EC1.24
DRLPOS_MICRO: D15.1 R15.1 R112.2 R116.2 U10.119 | length 148.3
  Top Layer w10: R112.2@961.5,1700 1029.27,1700 1030.53,1698.74 D15.1@1030.53,1620
DRLPOS_NTC: C65.1 EC1.28 R133.1 | length 1101.7
  Top Layer w25: v1(816.5,582.75) C65.1@816.5,616.06 884.89,616.06 R133.1@885,615.95
  Signal Layer 4 w10: v1(540,585) 555,570 803.74,570 v1(816.5,582.75)
  Bottom Layer w20: EC1.28@-160.24,612.99 477.01,612.99 505,585 v1(540,585)
DRLPOS_RBIN: C57.1 EC1.26 R132.1 | length 1140.8
  Top Layer w20: C57.1@817.99,710 v1(851.5,710) R132.1@890,710
  Signal Layer 4 w10: v1(505,680) 525,660 826.06,660 851.5,685.43 v1(851.5,710)
  Bottom Layer w25: EC1.26@-160.24,712.99 472.01,712.99 v1(505,680)
DRLPOSPWM: R36.1 U10.45
EN0RXI_N: U10.53
EN0RXI_P: U10.54
EN0TXO_N: U10.56
EN0TXO_P: U10.57
FB1: C13.2 R3.1 R10.2 U1.25 | length 240
  Top Layer w10: U1.25@2499.49,1656.1 2522.99,1656.1 2531.76,1647.34 C13.2@2531.76,1555.24 R10.2@2587.76,1555.24 R3.1@2643.76,1555.24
